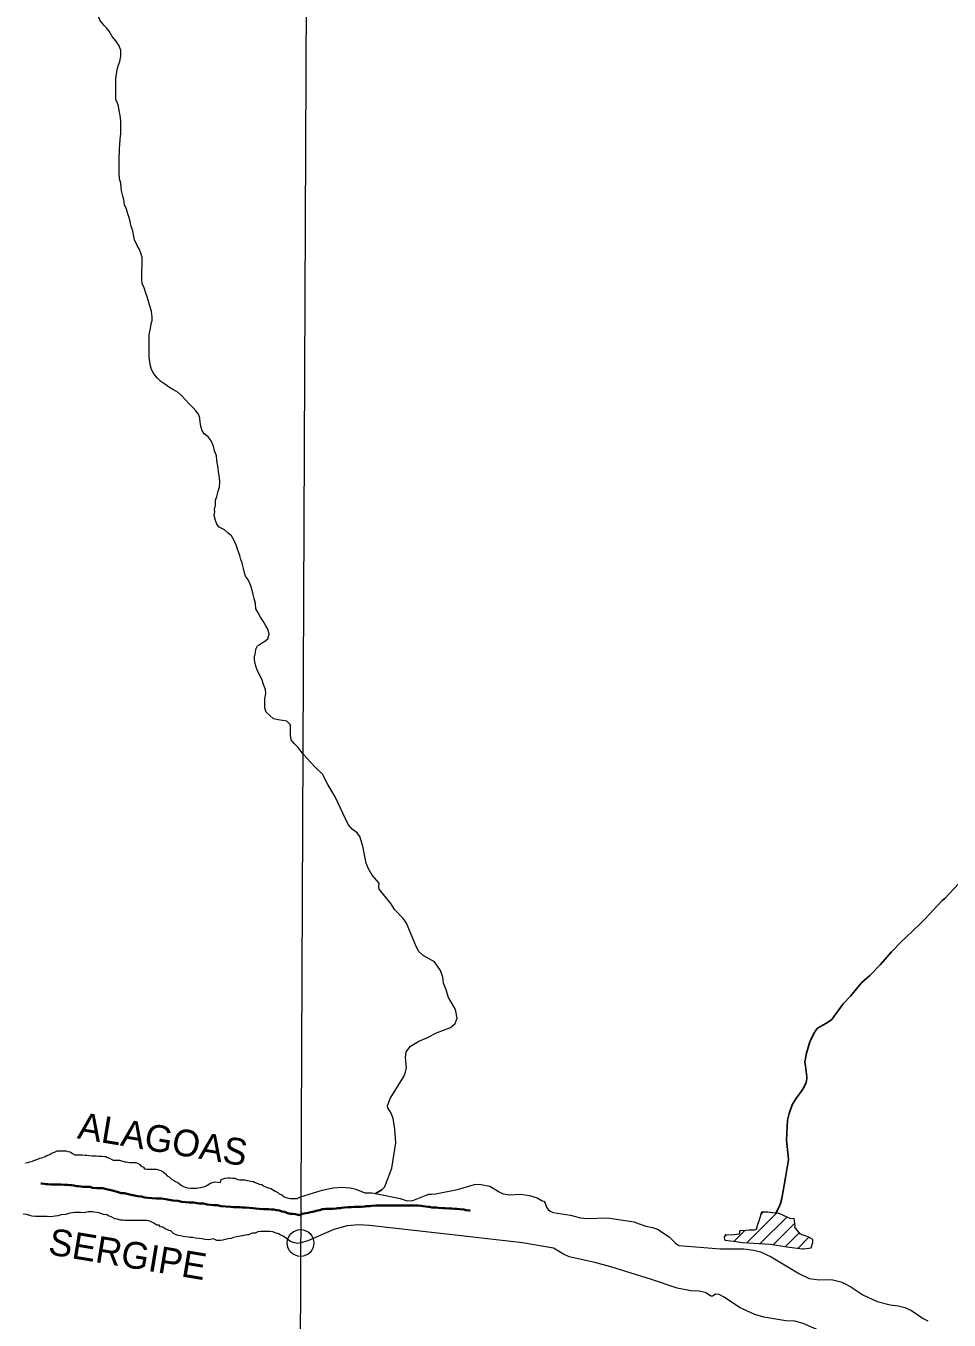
# Model space of a CAD drawing. Extents: x 553962 to 842807, y 8883888 to 9032388.
# Drawn here: x 595745 to 598511, y 8904160 to 8908040 of the extents above; entities that cross this region are included whole.
import ezdxf
from ezdxf.enums import TextEntityAlignment as Align

# ---------------------------------------------------------------- set-up
doc = ezdxf.new("R2010")
doc.units = 0
doc.header["$LTSCALE"] = 160
doc.header["$PDMODE"] = 32
doc.header["$PDSIZE"] = 80
doc.linetypes.add('LONG_DASH_SHORT_DASH', pattern=[9.9, 6, -1.2, 1.5, -1.2])
doc.layers.add('6', color=7, linetype='Continuous', lineweight=13)

msp = doc.modelspace()

# ---------------------------------------------------------------- linework, layer by layer
at = {"layer": '6'}
for p, q in [((597009.3, 8905170.6), (597009.5, 8905170.5)), ((597905.6, 8904392.3), (597995.3, 8904482)), ((597945.7, 8904390), (598025, 8904469.3)), ((597946.4, 8904475.5), (597954.7, 8904483.9)), ((597867.6, 8904396.8), (597899.4, 8904428.5)), ((597984.9, 8904386.8), (598049.1, 8904451)), ((598021.1, 8904380.5), (598062.5, 8904421.9)), ((597838.3, 8904409.9), (597844.2, 8904415.7)), ((598059, 8904376), (598091.6, 8904408.6))]:
    msp.add_line(p, q, dxfattribs=at)
for points in [[(596655.5, 8924715.8), (596593.3, 8909930.3), (596541.3, 8898204.5)], [(596014.3, 8907828.6), (596014.4, 8907881.9), (596016.5, 8907895.9), (596018.1, 8907906.9), (596021.6, 8907919.9), (596026.2, 8907932.8), (596029.8, 8907948.8), (596029.8, 8907966.3), (596024.4, 8907980.4), (596014.5, 8907995), (596004, 8908008), (595994.1, 8908024.1), (595986.1, 8908034.1), (595979.2, 8908041.2), (595966.7, 8908056.8), (595963.3, 8908066.3), (595963.8, 8908080.8), (595967.9, 8908092.8), (595975, 8908108.8), (595978.5, 8908119.2)], [(596049.9, 8907479.9), (596046.2, 8907490.3), (596040.2, 8907503.9), (596038.8, 8907519.4), (596035.3, 8907529.4), (596031.9, 8907545.5), (596030.4, 8907555.5), (596029.5, 8907568.5), (596025.6, 8907582), (596024.6, 8907598.1), (596024.9, 8907649.1), (596025.4, 8907658.6), (596026, 8907674.1), (596026.5, 8907683.6), (596027.6, 8907700.1), (596029.2, 8907716.6), (596029.4, 8907756.2), (596027.9, 8907771.7), (596025, 8907786.7), (596022.6, 8907799.7), (596019.1, 8907808.8), (596014.2, 8907819.3), (596014.3, 8907828.6)], [(596115.7, 8907204.3), (596113.9, 8907210.7), (596108, 8907227.8), (596104.5, 8907239.3), (596099.1, 8907254.8), (596093.7, 8907267.4), (596092.7, 8907279.4), (596093, 8907346), (596090.6, 8907355.5), (596085.1, 8907369.5), (596078.2, 8907382.1), (596070.8, 8907398.6), (596067.8, 8907413.7), (596065.4, 8907425.2), (596059.4, 8907441.7), (596058, 8907454.7), (596055, 8907464.3), (596049.9, 8907479.9)], [(596117.5, 8907024.2), (596116.1, 8907034), (596114.2, 8907044.6), (596114.5, 8907115.1), (596118.1, 8907133.1), (596120.6, 8907146.6), (596123.2, 8907157.1), (596123.2, 8907168.1), (596121.3, 8907184.2), (596117.4, 8907198.2), (596115.7, 8907204.3)], [(596271.3, 8906832.7), (596268.8, 8906840.6), (596267.4, 8906852.6), (596266, 8906863.6), (596262.5, 8906875.6), (596254.5, 8906886.2), (596246.1, 8906895.2), (596235.1, 8906906.3), (596222.2, 8906920.4), (596211.2, 8906932.4), (596201.2, 8906941), (596187.3, 8906949.1), (596175.3, 8906955.7), (596161.8, 8906966.2), (596149.8, 8906973.8), (596139.9, 8906984.4), (596128.4, 8906996.9), (596121.5, 8907010), (596118, 8907020.5), (596117.5, 8907024.2)], [(596279.7, 8906817), (596272.3, 8906829.5), (596271.3, 8906832.7)], [(596461.2, 8906005.4), (596461.2, 8906022.7), (596463.8, 8906039.2), (596463.4, 8906051.2), (596457.4, 8906065.3), (596453.5, 8906078.3), (596444.6, 8906095.4), (596439.1, 8906106.9), (596433.7, 8906120.9), (596429.8, 8906138.5), (596429.8, 8906149), (596432.9, 8906162), (596433.9, 8906171.5), (596439.5, 8906182), (596451, 8906189.9), (596461, 8906195.4), (596470.1, 8906202.3), (596474.2, 8906216.8), (596471.2, 8906229.4), (596464.2, 8906241.4), (596455.8, 8906256), (596447.9, 8906268), (596439.9, 8906282.6), (596434.5, 8906292.6), (596433, 8906308.7), (596429.1, 8906323.7), (596426.2, 8906335.2), (596422.7, 8906348.8), (596419.3, 8906361.8), (596413.8, 8906373.3), (596408.8, 8906382.4), (596403.4, 8906390.9), (596399.9, 8906400.4), (596397, 8906413.4), (596393.6, 8906429), (596389.6, 8906440), (596386.2, 8906452.6), (596379.7, 8906468.6), (596376.3, 8906481.6), (596368.8, 8906497.2), (596361.4, 8906511.2), (596351.4, 8906519.3), (596340, 8906529.4), (596324, 8906537.5), (596317.3, 8906546.3), (596312.9, 8906557.6), (596309.7, 8906572.8), (596311, 8906582.9), (596310.7, 8906590.6), (596312.8, 8906603.1), (596313.4, 8906618.6), (596316.9, 8906629.1), (596321.5, 8906645.1), (596325.6, 8906657.6), (596326.1, 8906673.6), (596325.7, 8906686.1), (596321.8, 8906703.6), (596321.3, 8906715.7), (596317.4, 8906737.2), (596316.5, 8906750.7), (596310, 8906765.8), (596307.1, 8906779.8), (596300.2, 8906796.3), (596291.2, 8906807.9), (596279.7, 8906817)], [(596838.8, 8905408.9), (596804, 8905452.2), (596802.6, 8905456.8), (596803.3, 8905469.9), (596782.8, 8905493.9), (596770.6, 8905515.5), (596764.7, 8905530.2), (596754.3, 8905581.4), (596745.9, 8905609.6), (596737.4, 8905621.2), (596722.8, 8905631.7), (596710.6, 8905646), (596672.1, 8905729.1), (596650.2, 8905765.8), (596633.6, 8905797.4), (596611.2, 8905818.6), (596577.4, 8905855.5), (596559.7, 8905877.5), (596548.7, 8905888.6), (596540.2, 8905900.2), (596538.3, 8905914.2), (596537.9, 8905930.7), (596537.5, 8905945.2), (596527, 8905955.3), (596513.5, 8905957.9), (596500.5, 8905959.4), (596487, 8905962.5), (596476, 8905972.6), (596464.6, 8905983.1), (596461.1, 8905995.7), (596461.2, 8906005.4)], [(596792.7, 8904540.1), (596811.4, 8904551.1), (596818.4, 8904557.4), (596822.7, 8904565.5), (596841.5, 8904615.9), (596853.2, 8904691.8), (596850.7, 8904732.7), (596845.1, 8904764.5), (596839.3, 8904781), (596829.4, 8904796.5), (596828.9, 8904802.2), (596837.1, 8904824.7), (596877.1, 8904890.7), (596882.8, 8904903.4), (596885.5, 8904918), (596882.5, 8904946.3), (596884.2, 8904964.5), (596897.9, 8904982), (596922.6, 8904996.6), (596946.5, 8905006.2), (596975.3, 8905021.5), (597017.5, 8905037.8), (597031.8, 8905049.4), (597037, 8905065), (597032.3, 8905091.9), (597011.4, 8905127.4), (597004.9, 8905150.7), (596996.7, 8905170.4), (596994.1, 8905188.6), (596987.3, 8905208), (596969.8, 8905234), (596935.4, 8905253.2), (596921.5, 8905266.1), (596912.2, 8905285.1), (596886, 8905350.5), (596875.4, 8905364.7), (596850.4, 8905390), (596838.8, 8905408.9)], [(595744.1, 8904632.1), (595751.7, 8904633.1), (595756.2, 8904634.6), (595760.7, 8904636), (595765.2, 8904637), (595769.2, 8904639), (595774.7, 8904640.4), (595781.2, 8904642.4), (595786.8, 8904645.4), (595793.3, 8904646.3), (595802.8, 8904650.3), (595807.8, 8904653.7), (595816.9, 8904657.2), (595821.4, 8904660.7), (595830.4, 8904663.6), (595839, 8904668.1), (595845, 8904668), (595850, 8904668), (595858, 8904667.9), (595866, 8904667.4), (595870.5, 8904665.8), (595877.5, 8904664.8), (595884.9, 8904659.7), (595891.4, 8904656.2), (595899.4, 8904656.1), (595903.4, 8904656.1), (595910.9, 8904656.1), (595914.9, 8904656), (595922.9, 8904655), (595927.4, 8904654.4), (595934.9, 8904653.9), (595943.4, 8904652.3), (595951.4, 8904652.3), (595956.4, 8904652.3), (595963.4, 8904652.2), (595973.4, 8904651.6), (595980.4, 8904651.1), (595984.9, 8904650.6), (595989.4, 8904647.5), (595995.3, 8904646), (596002.3, 8904641.9), (596006.8, 8904639.9), (596012.8, 8904639.9), (596025.8, 8904639.8), (596041.3, 8904635.2), (596045.8, 8904634.6), (596050.3, 8904633.6), (596056.3, 8904633.1), (596063.8, 8904633), (596067.8, 8904633), (596074.3, 8904632.4), (596079.3, 8904630.4), (596086.2, 8904626.9), (596090.2, 8904622.3), (596097.2, 8904619.3), (596100.7, 8904614.2), (596107.2, 8904613.2), (596113.7, 8904613.2), (596120.7, 8904613.1), (596124.7, 8904613.1), (596128.7, 8904613.1), (596136.2, 8904613), (596142.2, 8904611), (596149.6, 8904608.4), (596156.1, 8904604.4), (596163.6, 8904599.3), (596168, 8904593.3), (596174.5, 8904590.2), (596180.5, 8904583.7), (596186.9, 8904580.1), (596193.4, 8904576.1), (596197.9, 8904574.1), (596204.4, 8904570), (596211.3, 8904563.4), (596217.3, 8904560.4), (596222.8, 8904558.9), (596229.8, 8904557.3), (596238.8, 8904556.3), (596245.3, 8904556.2), (596249.3, 8904556.2), (596255.8, 8904556.1), (596260.3, 8904556.6), (596268.3, 8904557.6), (596272.8, 8904559), (596280.8, 8904561), (596288.9, 8904564.4), (596292.9, 8904567.9), (596298.4, 8904570.9), (596307, 8904574.3), (596312, 8904575.3), (596327, 8904573.2), (596331.5, 8904582.7), (596337.5, 8904584.1)], [(596337.5, 8904584.1), (596341.6, 8904585.6), (596350.1, 8904586.6), (596357.6, 8904586.5), (596364.6, 8904586), (596371.1, 8904585.9), (596379.5, 8904581.9), (596386.5, 8904581.3), (596393.5, 8904581.3), (596401.5, 8904580.7), (596408, 8904579.2), (596414, 8904578.1), (596419, 8904576.6), (596427, 8904575.5), (596432, 8904572.5), (596440, 8904569.4), (596444.5, 8904567.9), (596452, 8904566.9), (596457.4, 8904563.3), (596468.4, 8904558.2), (596478.9, 8904554.7), (596487.3, 8904550.1), (596492.3, 8904546.6), (596500.3, 8904543), (596504.3, 8904539), (596511.7, 8904535.4), (596519.2, 8904529.4), (596523.7, 8904527.8), (596531.7, 8904525.8), (596538.2, 8904524.7), (596545.2, 8904524.7), (596549.2, 8904524.7), (596554.2, 8904525.1), (596558.2, 8904525.1), (596568.1, 8904529.4), (596633, 8904549.7), (596665.5, 8904556.5), (596692.3, 8904558.4), (596717.2, 8904557), (596733.8, 8904552.4)], [(596733.8, 8904552.4), (596760.4, 8904542.1), (596781.9, 8904541.7), (596822.9, 8904534.3)], [(596822.7, 8904565.5), (596818.4, 8904557.4), (596811.4, 8904551.1), (596792.7, 8904540.1)], [(596823.3, 8904534.6), (596822.9, 8904534.3), (596866.1, 8904524.6), (596887.5, 8904518.1), (596904.4, 8904518.5), (596944.7, 8904535.2), (596952.2, 8904537.4), (596959.2, 8904537.7), (596972.2, 8904538.7), (597038.5, 8904552.3), (597088.9, 8904566.9), (597103.5, 8904567.8), (597135.1, 8904562.2), (597163.3, 8904544.4), (597175.5, 8904538.6), (597195.2, 8904535.8), (597227.3, 8904537.4), (597253.9, 8904534.1), (597277.1, 8904527.3), (597291.9, 8904517.4), (597296.9, 8904516.7), (597300.6, 8904511.3), (597305.1, 8904499.1), (597310, 8904491.8), (597315.9, 8904486.6), (597325.4, 8904483.2), (597377.2, 8904474.8), (597406.8, 8904466.6), (597425.4, 8904464.6), (597488, 8904467), (597567.9, 8904454.9)], [(596113, 8904457.9), (596106, 8904458.5), (596097.5, 8904459.1), (596092.5, 8904459.1), (596084.5, 8904459.1), (596079.5, 8904459.2), (596067.5, 8904459.2), (596057, 8904459.3), (596050, 8904459.4), (596042, 8904459.4), (596036.5, 8904459.5), (596028, 8904459.5), (596020, 8904462.6), (596012, 8904463.6), (596005, 8904467.7), (595998.5, 8904470.7), (595991.5, 8904472.8), (595987.1, 8904475.8), (595977.6, 8904476.9), (595969.6, 8904479.9), (595965.1, 8904481.5), (595958.6, 8904482.5), (595950.1, 8904484.1), (595945.1, 8904485.1), (595936.6, 8904485.2), (595932.1, 8904485.2), (595920.1, 8904482.3), (595908.6, 8904483.3), (595897.6, 8904483.4), (595892.1, 8904482.9), (595885.1, 8904482), (595877, 8904480.5), (595865, 8904477.1), (595851, 8904476.2), (595840.5, 8904473.3), (595832.5, 8904471.8), (595827, 8904470.9), (595816.4, 8904470.4), (595808.4, 8904470.5), (595798.4, 8904470.5), (595789.4, 8904470.6), (595783.9, 8904470.6), (595773.9, 8904470.7), (595763.9, 8904472.3), (595756.9, 8904473.8), (595747, 8904477.4), (595737, 8904478)], [(596137.9, 8904445.3), (596128.4, 8904450.8), (596120.5, 8904454.9), (596113, 8904457.9)], [(596412.8, 8904415.9), (596408.8, 8904415.9), (596401.3, 8904414.5), (596394.3, 8904413), (596387.2, 8904411.6), (596383.2, 8904410.6), (596376.2, 8904409.6), (596366.7, 8904408.2), (596360.2, 8904405.2), (596351.2, 8904404.3), (596347.2, 8904402.8), (596341.2, 8904401.9), (596335.1, 8904399.9), (596328.6, 8904398.9), (596324.1, 8904398.5), (596317.1, 8904398.5), (596307.2, 8904403.6), (596293.1, 8904401.2), (596281.1, 8904402.3), (596273.1, 8904403.8), (596264.6, 8904405.4), (596253.7, 8904406.4), (596244.7, 8904407.5), (596236.7, 8904408.1), (596232.2, 8904409.1), (596224.2, 8904410.2), (596216.7, 8904411.2), (596208.7, 8904412.8), (596201.2, 8904414.3), (596196.2, 8904415.8), (596188.7, 8904418.9), (596184.2, 8904422.9), (596179.3, 8904428), (596173.3, 8904429), (596167.8, 8904432.1), (596160.3, 8904435.1), (596155.8, 8904438.6), (596148.8, 8904439.7), (596144.9, 8904444.7), (596137.9, 8904445.3)], [(597784.5, 8904240.9), (597780.8, 8904243.5), (597763, 8904246.9), (597737.7, 8904248), (597696.4, 8904255.7), (597619.9, 8904282.1), (597498.2, 8904319.6), (597450, 8904332.9), (597372.6, 8904350.3), (597356, 8904357.7), (597326.5, 8904376.3), (597232.9, 8904391.8), (597058.1, 8904411.6), (596775.1, 8904444.1), (596742.4, 8904446), (596707.5, 8904442.8), (596667.4, 8904431.6), (596590.1, 8904397.6), (596568.1, 8904391.5), (596558.7, 8904389.9), (596551.2, 8904391.5), (596544.2, 8904394), (596537.7, 8904395.6), (596530.7, 8904401.1), (596526.2, 8904404.6), (596520.3, 8904409.2), (596515.8, 8904412.2), (596506.8, 8904415.8), (596502.3, 8904419.3), (596492.4, 8904422.4), (596485.4, 8904425.4), (596475.9, 8904426), (596467.4, 8904426.1), (596458.4, 8904426.1), (596449.4, 8904426.2), (596440.4, 8904425.2), (596431.8, 8904421.3), (596424.8, 8904421.3), (596420.3, 8904419.9), (596412.8, 8904415.9)], [(597567.9, 8904454.9), (597572.2, 8904452.6), (597602.6, 8904441.6), (597622.9, 8904438.2), (597638, 8904432.9), (597672.2, 8904410.2), (597691.4, 8904390.6), (597701.7, 8904384.3), (597826.9, 8904374.3), (597896.6, 8904373.8), (597926.2, 8904370), (597946.7, 8904364.9), (597978.4, 8904349.8), (598062.8, 8904298.6), (598092.1, 8904285.4), (598121.7, 8904280.6), (598145.7, 8904281.8), (598162.6, 8904280.9), (598187.1, 8904274.8), (598198.3, 8904270.4), (598217.2, 8904259.9), (598252.8, 8904236.5), (598295.7, 8904216.1), (598334.6, 8904205.9), (598358.9, 8904203.3), (598378.5, 8904198.1), (598398.6, 8904189.3), (598434, 8904165.6), (598448.2, 8904158.3)], [(598520.2, 8903910.4), (598487.1, 8903943.5), (598436.5, 8903981.5), (598405, 8904009.5), (598386.5, 8904016.8), (598347.6, 8904027.2), (598321.2, 8904038.2), (598293.7, 8904056), (598254.9, 8904085.9), (598238.1, 8904096), (598214.8, 8904104.4), (598122.2, 8904129.2), (598073.8, 8904150.4), (598048.8, 8904157.2), (598021.9, 8904158.5), (597956.3, 8904169.2), (597929.3, 8904177.5), (597883.8, 8904198.6), (597837.6, 8904229.6), (597822.4, 8904236.9), (597812.2, 8904237.9), (597802.9, 8904232.5), (597797.6, 8904231.9), (597784.5, 8904240.9)]]:
    msp.add_lwpolyline(points, dxfattribs=at)
at = {"layer": '6', "lineweight": 25}
for points in [[(598811.5, 8905757.4), (598733.5, 8905676.3), (598498.6, 8905424.2), (598490.9, 8905418), (598439.8, 8905363.3), (598425.4, 8905349.3)], [(598425.4, 8905349.3), (598382.1, 8905307.4), (598370, 8905296.7), (598339.1, 8905264), (598305.9, 8905226), (598273.9, 8905193.3), (598249.7, 8905171.9), (598243, 8905164.1)], [(598243, 8905164.1), (598215.7, 8905131.8), (598194.5, 8905108.4), (598159.2, 8905060.4), (598142.4, 8905049.3), (598117.3, 8905035), (598111.1, 8905027.6), (598105.9, 8905019.5), (598097.1, 8905000.6)], [(598097.1, 8905000.6), (598094.2, 8904994.3), (598084, 8904960.9), (598079.1, 8904934.7), (598081, 8904921.7)], [(598081, 8904921.7), (598085.6, 8904889.7), (598085.6, 8904884.2), (598082.7, 8904873.1), (598076, 8904857.5), (598071.3, 8904849.5), (598052.2, 8904824.1), (598041.5, 8904805.9), (598031.7, 8904779.5), (598027.3, 8904760), (598024.5, 8904700), (598029.9, 8904642.3), (598029.5, 8904633.9), (598026.3, 8904618.1), (598021.2, 8904587.6)], [(598021.2, 8904587.6), (598010.6, 8904524.8), (598006.1, 8904509.6), (598000.4, 8904495.6), (597993.4, 8904482.7)]]:
    msp.add_lwpolyline(points, dxfattribs=at)
at = {"layer": '6', "linetype": 'LONG_DASH_SHORT_DASH', "lineweight": 35}
for points in [[(596403.1, 8904497.6), (596393.1, 8904498.1), (596385.2, 8904498.7), (596380.2, 8904498.7), (596375.2, 8904499.2), (596367.2, 8904499.3), (596358.7, 8904499.8), (596344.2, 8904500.9), (596330.2, 8904502), (596318.2, 8904504.5), (596307.2, 8904505.1), (596298.2, 8904506.1), (596288.7, 8904507.2), (596278.2, 8904509.8), (596264.2, 8904510.3), (596247.2, 8904512.9), (596234.7, 8904513), (596223.2, 8904513.5), (596212.2, 8904514.6), (596200.3, 8904518.2), (596185.3, 8904519.2), (596169.8, 8904521.8), (596151.3, 8904524.9), (596136.3, 8904525), (596122.8, 8904526.1), (596111.8, 8904527.1), (596101.3, 8904528.2), (596090.4, 8904531.3), (596079.4, 8904531.8), (596065.9, 8904534.4), (596051.9, 8904538), (596040.4, 8904540.5), (596030.9, 8904541.1), (596021.4, 8904543.6), (596012, 8904546.7), (596000, 8904549.8), (595987, 8904552.8), (595974.5, 8904555.4), (595957.5, 8904556), (595944.5, 8904557.1), (595937.6, 8904559.6), (595929.5, 8904559.6), (595924, 8904559.7), (595915.6, 8904560.2), (595909.6, 8904560.7), (595903.1, 8904561.8), (595897.1, 8904562.3), (595889.1, 8904563.9), (595883.1, 8904564.4), (595877.1, 8904564.9), (595870.1, 8904566), (595860.6, 8904566), (595850.1, 8904566.6), (595840.6, 8904567.1), (595830.1, 8904567.2), (595819.1, 8904567.2), (595811.1, 8904567.8), (595805.6, 8904567.8), (595800.1, 8904568.8), (595791.6, 8904569.4), (595790.2, 8904569.7)], [(596573, 8904478.7), (596564, 8904475.2), (596553, 8904478.3), (596546, 8904478.8), (596537, 8904479.3), (596527, 8904481.9), (596519.6, 8904484.9), (596512.1, 8904486), (596504.6, 8904488.5), (596497.1, 8904489.6), (596487.6, 8904492.1), (596479.1, 8904492.2), (596471.6, 8904492.7), (596456.6, 8904493.3), (596443.6, 8904493.9), (596434.1, 8904494.9), (596425.1, 8904495.5), (596414.6, 8904496.5), (596403.1, 8904497.6)], [(597057.4, 8904492), (597045.7, 8904492.5), (597036, 8904494), (597030.4, 8904494), (597021.8, 8904494.5), (597014.2, 8904494.5), (597000.4, 8904495.6), (596993.3, 8904496.1), (596981.1, 8904496.6), (596975, 8904497.6), (596965.8, 8904498.1), (596961.2, 8904498.1), (596954.1, 8904499.7), (596950, 8904500.2), (596942.9, 8904500.7), (596935.3, 8904501.7), (596929.7, 8904502.7), (596920, 8904503.7), (596907.3, 8904503.7), (596895.6, 8904503.7), (596890, 8904503.7), (596880.3, 8904503.7), (596874.2, 8904503.7), (596857.9, 8904503.7), (596850.8, 8904503.7), (596839.1, 8904503.7), (596833, 8904503.7), (596821.8, 8904503.7), (596815.7, 8904503.7), (596801.4, 8904503.7), (596793.8, 8904503.7), (596782.1, 8904502.7), (596776, 8904502.2), (596765.8, 8904501.7), (596760.7, 8904500.7), (596750.6, 8904499.6), (596741.9, 8904499.6), (596737.3, 8904499.6), (596728.7, 8904499.6), (596720.5, 8904498.6), (596710.8, 8904498.6), (596699.7, 8904498.1), (596691, 8904496.6), (596686.4, 8904496.1), (596679.3, 8904495.6), (596675.2, 8904494.5), (596665.6, 8904494), (596659.5, 8904494), (596654.4, 8904494), (596648.8, 8904494), (596642.7, 8904494), (596637.1, 8904492.5), (596633, 8904492.5), (596625.9, 8904490.4), (596620.3, 8904489.4), (596614.7, 8904487.9), (596608.6, 8904486.3), (596603.5, 8904484.8), (596597.4, 8904483.8), (596591.3, 8904482.3), (596585.2, 8904480.7), (596579.1, 8904479.7), (596573, 8904478.7), (596573, 8904478.7), (596573, 8904478.7)], [(597076.6, 8904488.8), (597073.7, 8904489.4), (597063, 8904490.4), (597057.4, 8904492)]]:
    msp.add_lwpolyline(points, dxfattribs=at)
at = {"layer": '6'}
msp.add_lwpolyline([(598076.1, 8904374.3), (598098.6, 8904377.3), (598102.8, 8904393.2), (598103.1, 8904402.4), (598089.5, 8904409.8), (598071, 8904415.8), (598065, 8904418.6), (598052.1, 8904435.2), (598049.2, 8904436.8), (598050, 8904442.7), (598047.6, 8904465), (598036.8, 8904463.8), (598004.4, 8904478.8), (597993.7, 8904482.5), (597989.2, 8904480.8), (597968.7, 8904483.6), (597949.6, 8904484), (597945.8, 8904474), (597941.6, 8904457.1), (597937.6, 8904447), (597933.3, 8904431.5), (597927.5, 8904429.7), (597912, 8904430), (597894.4, 8904427.9), (597885.2, 8904428.9), (597883.8, 8904426.4), (597882.9, 8904420.8), (597881.3, 8904418.1), (597859.9, 8904414.8), (597840.3, 8904416), (597837.6, 8904407.7), (597838.4, 8904401.7), (597841.9, 8904400), (597856, 8904397.5), (597873.8, 8904396.3), (597891.4, 8904393.1), (597976.5, 8904388.3), (598025.4, 8904379.8), (598072.1, 8904374.5)], close=True, dxfattribs=at)
msp.add_point((596568.1, 8904391.5), dxfattribs=at)

# ---------------------------------------------------------------- texts
for s, p in [('ALAGOAS', (596148.9, 8904663.4)), ('SERGIPE', (596043.6, 8904319))]:
    msp.add_text(s, height=80, rotation=350.533, dxfattribs=at).set_placement(p, align=Align.CENTER)

doc.saveas('drawing.dxf')
